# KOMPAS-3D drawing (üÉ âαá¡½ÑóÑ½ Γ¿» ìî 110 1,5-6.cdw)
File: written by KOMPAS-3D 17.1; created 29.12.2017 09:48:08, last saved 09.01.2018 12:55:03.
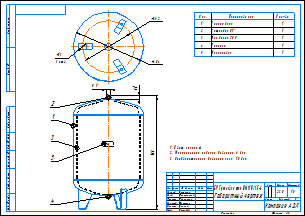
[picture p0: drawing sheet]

Sheet 1: A3, landscape, title-block layout from C:\Лощинин\GRAPHIC.LYT style 1

Title block, sheet 1: name: БР Гранлевел тип НМ 110/1,5-6 / Габаритный чертеж; mass: 23,8; sheets: 1; sheet format: A3; stored path: \\Fsk1\files\АП\20_PKO\02_Насосное направление\Разработка\04_Проекты разные\Баки\КД действующая\Баки Flexcon R\Компас\Чертежи\БР Гранлевел тип НМ 110 1,5-6.cdw; drawn by: Лощинин; checked by: Хантимеров

Views: Проекционный вид 3
Referenced files in \\Fsk1\files\АП\20_PKO\02_Насосное направление\Разработка\04_Проекты разные\Баки\КД действующая\Баки Flexcon R\Компас\: 110 литров.a3d, 16116_Flexcon_110_1-6.m3d
Referenced files in C:\Лощинин\: GRAPHIC.LYT
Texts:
  IvAn
  ADL
  Поз.
  Кол-во
  Корпус бака
  Мембрана SBR
  Патрубок G1"
  Ниппель
  Маркировка
  АДЛ
  Цвет: красный
  Максимальное рабочее давление: 6 бар
  Предварительное давление газа: 1,5 бар
  ACAD_ISO03W100_RGB_223_127_255_SC_0.063_THICK_0.05
  ACAD_ISO03W100_RGB_223_127_255_SC_1_THICK_0.05
  Лит-Масса-Масштаб
  Материал-Предприятие
  Масштаб
  Изм.
  Лист
  № докум.
  Подп.
  Дата
  Лит.
  Разраб.
  Пров.
  Т.контр.
  Курлыкина
  Листов
  Нач.отд.
  Щетинин
  Н.контр.
  Долгов
  Утв.
  Рашидов
  Компания АДЛ
  Изменение
  Номер документа
  Подпись
  Обозначение документа
  Наименование изделия
  Масса изделия по ГОСТ 2.109-73
  Порядковый номер листа
  Общее количество листов в документе
  Характер работы, выполненной лицом, подписавшим документ
  Наименование или индекс предприятия, выпускающего документ
  Инв. № подл.
  Подп. и дата
  Взам. инв. №
  Инв. № дубл.
  Инвентарный номер подлинника по ГОСТ 2.501-68
  Подпись принявшего подлинник в отдел технической документации
  Инвентарный номер подлинника, взамен которого выпущен данный подлинник
  Инвентарный номер дубликата по ГОСТ 2.502-68
  Подпись принявшего дубликат в отдел технической документации
  Справ. №
  Перв. примен.
  Обозначение документа, взамен или на основании которого выпущен данный документ
  Обозначение документа, в котором впервые записан данный документ
  Подпись лица, копировавшего чертеж
  Обозначение формата листа
Dimensions and other numbers on the sheet: 1; 3; 2; 4; 5; 780; 21; 1:5; 23,8; 16116_Flexcon_110_1-6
